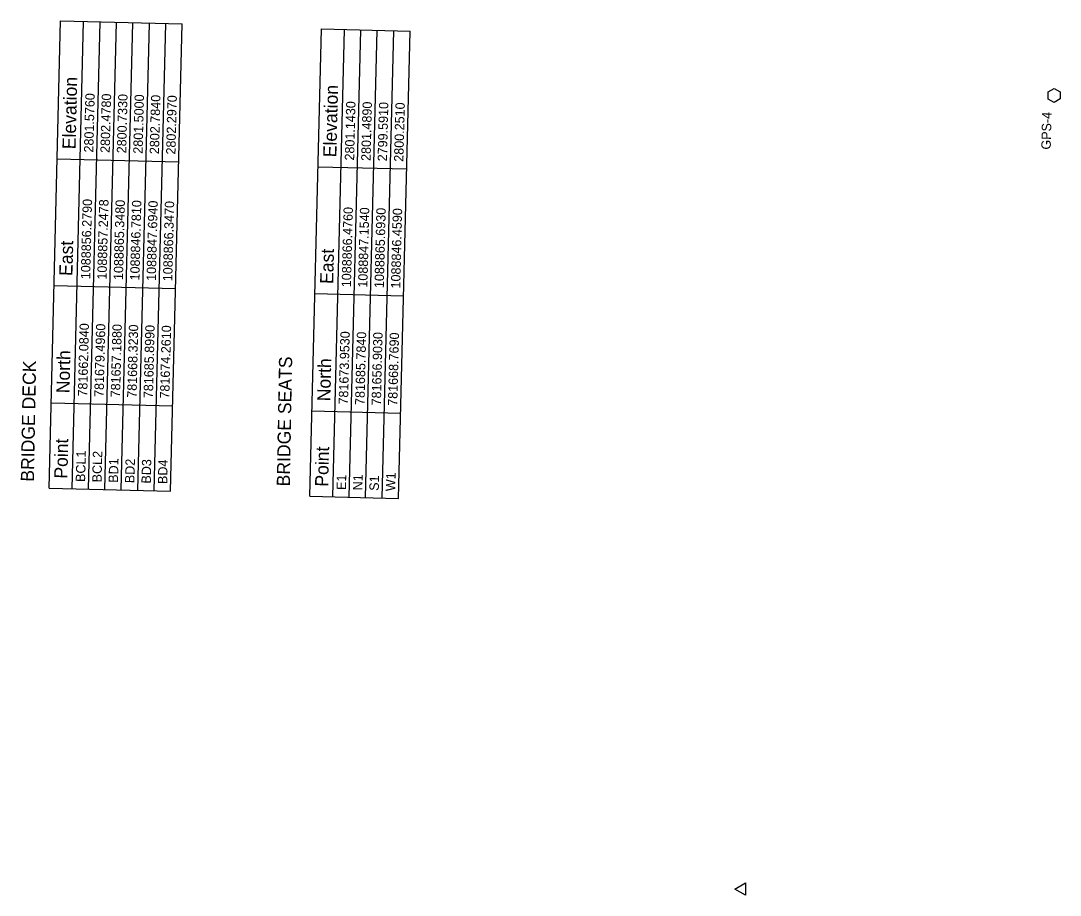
# Model space of a CAD drawing. Extents: x 1088366 to 1089341, y 781245 to 782648.
# Drawn here: x 1088464 to 1089017, y 782182 to 782648 of the extents above; entities that cross this region are included whole.
import ezdxf

# ---------------------------------------------------------------- set-up
doc = ezdxf.new("R2010")
doc.units = 0
for name, color, linetype in [('CTL Primary Horizontal and Vertical CELL', 7, 'Continuous'), ('CTL Primary Horizontal and Vertical Text', 7, 'Continuous'), ('Default', 7, 'Continuous'), ('Exist Right of Way Monument CELL', 7, 'Continuous')]:
    doc.layers.add(name, color=color, linetype=linetype)

msp = doc.modelspace()

# ---------------------------------------------------------------- linework, layer by layer
at = {"layer": 'CTL Primary Horizontal and Vertical CELL'}
msp.add_line((1089013.94, 782608.23), (1089013.94, 782608.23), dxfattribs=at)
msp.add_lwpolyline([(1089010.71, 782610.11), (1089013.96, 782611.92), (1089017.21, 782610.13), (1089017.16, 782606.41), (1089013.91, 782604.52), (1089010.71, 782606.33)], close=True, dxfattribs=at)
at = {"layer": 'Default'}
for p, q in [((1088478.64, 782399.08), (1088484.84, 782648)), ((1088484.84, 782648), (1088549.57, 782646.39)), ((1088484.84, 782648), (1088549.57, 782646.39)), ((1088484.84, 782648), (1088549.57, 782646.39)), ((1088484.84, 782648), (1088549.57, 782646.39)), ((1088484.84, 782648), (1088549.57, 782646.39)), ((1088490.88, 782398.77), (1088497.09, 782647.69)), ((1088499.63, 782398.55), (1088505.83, 782647.48)), ((1088499.63, 782398.55), (1088505.83, 782647.48)), ((1088499.63, 782398.55), (1088505.83, 782647.48)), ((1088499.63, 782398.55), (1088505.83, 782647.48)), ((1088508.38, 782398.34), (1088514.58, 782647.26)), ((1088508.38, 782398.34), (1088514.58, 782647.26)), ((1088508.38, 782398.34), (1088514.58, 782647.26)), ((1088508.38, 782398.34), (1088514.58, 782647.26)), ((1088517.12, 782398.12), (1088523.33, 782647.04)), ((1088517.12, 782398.12), (1088523.33, 782647.04)), ((1088517.12, 782398.12), (1088523.33, 782647.04)), ((1088517.12, 782398.12), (1088523.33, 782647.04)), ((1088525.87, 782397.9), (1088532.08, 782646.82)), ((1088525.87, 782397.9), (1088532.08, 782646.82)), ((1088525.87, 782397.9), (1088532.08, 782646.82)), ((1088525.87, 782397.9), (1088532.08, 782646.82)), ((1088534.62, 782397.68), (1088540.82, 782646.6)), ((1088534.62, 782397.68), (1088540.82, 782646.6)), ((1088534.62, 782397.68), (1088540.82, 782646.6)), ((1088534.62, 782397.68), (1088540.82, 782646.6)), ((1088543.37, 782397.46), (1088549.57, 782646.39)), ((1088543.37, 782397.46), (1088549.57, 782646.39)), ((1088543.37, 782397.46), (1088549.57, 782646.39)), ((1088543.37, 782397.46), (1088549.57, 782646.39)), ((1088617.54, 782394.8), (1088623.75, 782643.73)), ((1088623.75, 782643.73), (1088670.98, 782642.55)), ((1088623.75, 782643.73), (1088670.98, 782642.55)), ((1088623.75, 782643.73), (1088670.98, 782642.55)), ((1088623.75, 782643.73), (1088670.98, 782642.55)), ((1088623.75, 782643.73), (1088670.98, 782642.55)), ((1088629.79, 782394.5), (1088635.99, 782643.42)), ((1088638.54, 782394.28), (1088644.74, 782643.2)), ((1088638.54, 782394.28), (1088644.74, 782643.2)), ((1088638.54, 782394.28), (1088644.74, 782643.2)), ((1088638.54, 782394.28), (1088644.74, 782643.2)), ((1088647.28, 782394.06), (1088653.49, 782642.99)), ((1088647.28, 782394.06), (1088653.49, 782642.99)), ((1088647.28, 782394.06), (1088653.49, 782642.99)), ((1088647.28, 782394.06), (1088653.49, 782642.99)), ((1088656.03, 782393.84), (1088662.24, 782642.77)), ((1088656.03, 782393.84), (1088662.24, 782642.77)), ((1088656.03, 782393.84), (1088662.24, 782642.77)), ((1088656.03, 782393.84), (1088662.24, 782642.77)), ((1088664.78, 782393.63), (1088670.98, 782642.55)), ((1088664.78, 782393.63), (1088670.98, 782642.55)), ((1088664.78, 782393.63), (1088670.98, 782642.55)), ((1088664.78, 782393.63), (1088670.98, 782642.55)), ((1088483.01, 782574.52), (1088547.74, 782572.91)), ((1088621.92, 782570.25), (1088669.15, 782569.07)), ((1088481.33, 782507.04), (1088546.06, 782505.43)), ((1088620.23, 782502.77), (1088667.47, 782501.59)), ((1088479.77, 782444.56), (1088544.5, 782442.95)), ((1088618.68, 782440.29), (1088665.91, 782439.11)), ((1088478.64, 782399.08), (1088543.37, 782397.46)), ((1088617.54, 782394.8), (1088664.78, 782393.63))]:
    msp.add_line(p, q, dxfattribs=at)
at = {"layer": 'Exist Right of Way Monument CELL'}
msp.add_line((1088847.72, 782185.58), (1088847.72, 782185.58), dxfattribs=at)
msp.add_lwpolyline([(1088843.96, 782185.57), (1088849.59, 782188.83), (1088849.59, 782182.32)], close=True, dxfattribs=at)

# ---------------------------------------------------------------- texts
at = {"layer": 'CTL Primary Horizontal and Vertical Text'}
msp.add_text('GPS-4', height=5, rotation=88.5723, dxfattribs=at).set_placement((1089012.12, 782579.36))
at = {"layer": 'Default'}
for s, height, rotation, p in [('Elevation', 7, 88.5723, (1088492.76, 782579.53)), ('Elevation', 7, 88.5723, (1088631.67, 782575.26)), ('2801.5760', 5, 88.5723, (1088502.22, 782577.79)), ('2802.4780', 5, 88.5723, (1088510.97, 782577.58)), ('2800.7330', 5, 88.5723, (1088519.72, 782577.36)), ('2801.5000', 5, 88.5723, (1088528.46, 782577.14)), ('2802.7840', 5, 88.5723, (1088537.21, 782576.92)), ('2802.2970', 5, 88.5723, (1088545.96, 782576.7)), ('2801.1430', 5, 88.5723, (1088641.13, 782573.52)), ('2801.4890', 5, 88.5723, (1088649.88, 782573.3)), ('2799.5910', 5, 88.5723, (1088658.62, 782573.09)), ('2800.2510', 5, 88.5723, (1088667.37, 782572.87)), ('1088856.2790', 5, 88.5723, (1088500.54, 782510.32)), ('1088857.2478', 5, 88.5723, (1088509.29, 782510.1)), ('1088865.3480', 5, 88.5723, (1088518.03, 782509.88)), ('1088846.7810', 5, 88.5723, (1088526.78, 782509.66)), ('1088847.6940', 5, 88.5723, (1088535.53, 782509.44)), ('1088866.3470', 5, 88.5723, (1088544.28, 782509.23)), ('1088866.4760', 5, 88.5723, (1088639.45, 782506.04)), ('1088847.1540', 5, 88.5723, (1088648.19, 782505.82)), ('1088865.6930', 5, 88.5723, (1088656.94, 782505.61)), ('1088846.4590', 5, 88.5723, (1088665.69, 782505.39)), ('East', 7, 88.5723, (1088491.08, 782512.05)), ('East', 7, 88.5723, (1088629.99, 782507.78)), ('781662.0840', 5, 88.5723, (1088498.98, 782447.84)), ('781679.4960', 5, 88.5723, (1088507.73, 782447.62)), ('781657.1880', 5, 88.5723, (1088516.48, 782447.4)), ('781668.3230', 5, 88.5723, (1088525.22, 782447.18)), ('781685.8990', 5, 88.5723, (1088533.97, 782446.96)), ('781674.2610', 5, 88.5723, (1088542.72, 782446.75)), ('781673.9530', 5, 88.5723, (1088637.89, 782443.56)), ('781685.7840', 5, 88.5723, (1088646.64, 782443.34)), ('781656.9030', 5, 88.5723, (1088655.38, 782443.13)), ('781668.7690', 5, 88.5723, (1088664.13, 782442.91)), ('North', 7, 88.5723, (1088489.52, 782449.57)), ('BRIDGE SEATS', 7, 88.9484, (1088606.91, 782400.01)), ('BRIDGE DECK', 7, 88.9484, (1088470.59, 782402.51)), ('North', 7, 88.5723, (1088628.43, 782445.3)), ('Point', 7, 88.5723, (1088488.39, 782404.09)), ('BCL1', 5, 88.5723, (1088497.85, 782402.35)), ('BCL2', 5, 88.5723, (1088506.6, 782402.13)), ('Point', 7, 88.5723, (1088627.3, 782399.81)), ('BD1', 5, 88.5723, (1088515.34, 782401.91)), ('BD2', 5, 88.5723, (1088524.09, 782401.7)), ('BD3', 5, 88.5723, (1088532.84, 782401.48)), ('BD4', 5, 88.5723, (1088541.58, 782401.26)), ('W1', 5, 88.5723, (1088663, 782397.42)), ('E1', 5, 88.5723, (1088636.76, 782398.08)), ('N1', 5, 88.5723, (1088645.5, 782397.86)), ('S1', 5, 88.5723, (1088654.25, 782397.64))]:
    msp.add_text(s, height=height, rotation=rotation, dxfattribs=at).set_placement(p)

doc.saveas('drawing.dxf')
